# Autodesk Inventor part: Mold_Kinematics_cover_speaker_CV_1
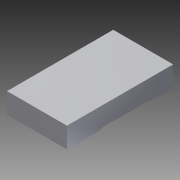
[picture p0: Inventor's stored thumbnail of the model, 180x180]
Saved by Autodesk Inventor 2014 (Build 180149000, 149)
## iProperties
Created: 2009-12
Part Number: Mold_Kinematics_cover_speaker_CV_1
Document SubType Name: Modeling
Designer: gaom
Density: 1 g/cm^3
Material: Generic
Appearance: Default
Author: gaom
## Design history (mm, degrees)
node "Mold_Kinematics_cover_speaker_CV_Base"
feature "Solid1::Mold_Kinematics_cover_speaker_CV_Base"
tag "TaggingFeature1"
body "Solid1"
